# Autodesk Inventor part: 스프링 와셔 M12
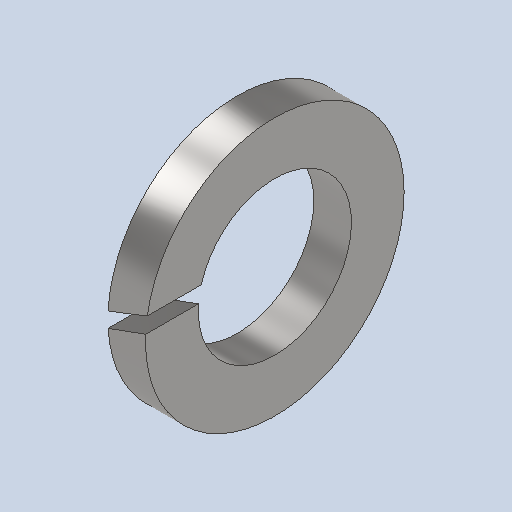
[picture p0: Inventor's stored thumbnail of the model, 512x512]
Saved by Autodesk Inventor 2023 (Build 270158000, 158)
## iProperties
Created: 2024-07
Part Number: 스프링 와셔 M12
Material: 강철, 연강
Description: 스프링 잠금 와셔
Document SubType Name: Modeling
Designer: home
Density: 7.85 g/cm^3
Appearance: 기본값
Author: jhkim
Sending System: Autodesk Inventor 2025
Preprocessor: ST-DEVELOPER v20
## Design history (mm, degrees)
feature "Solid1"
node "솔리드1"
